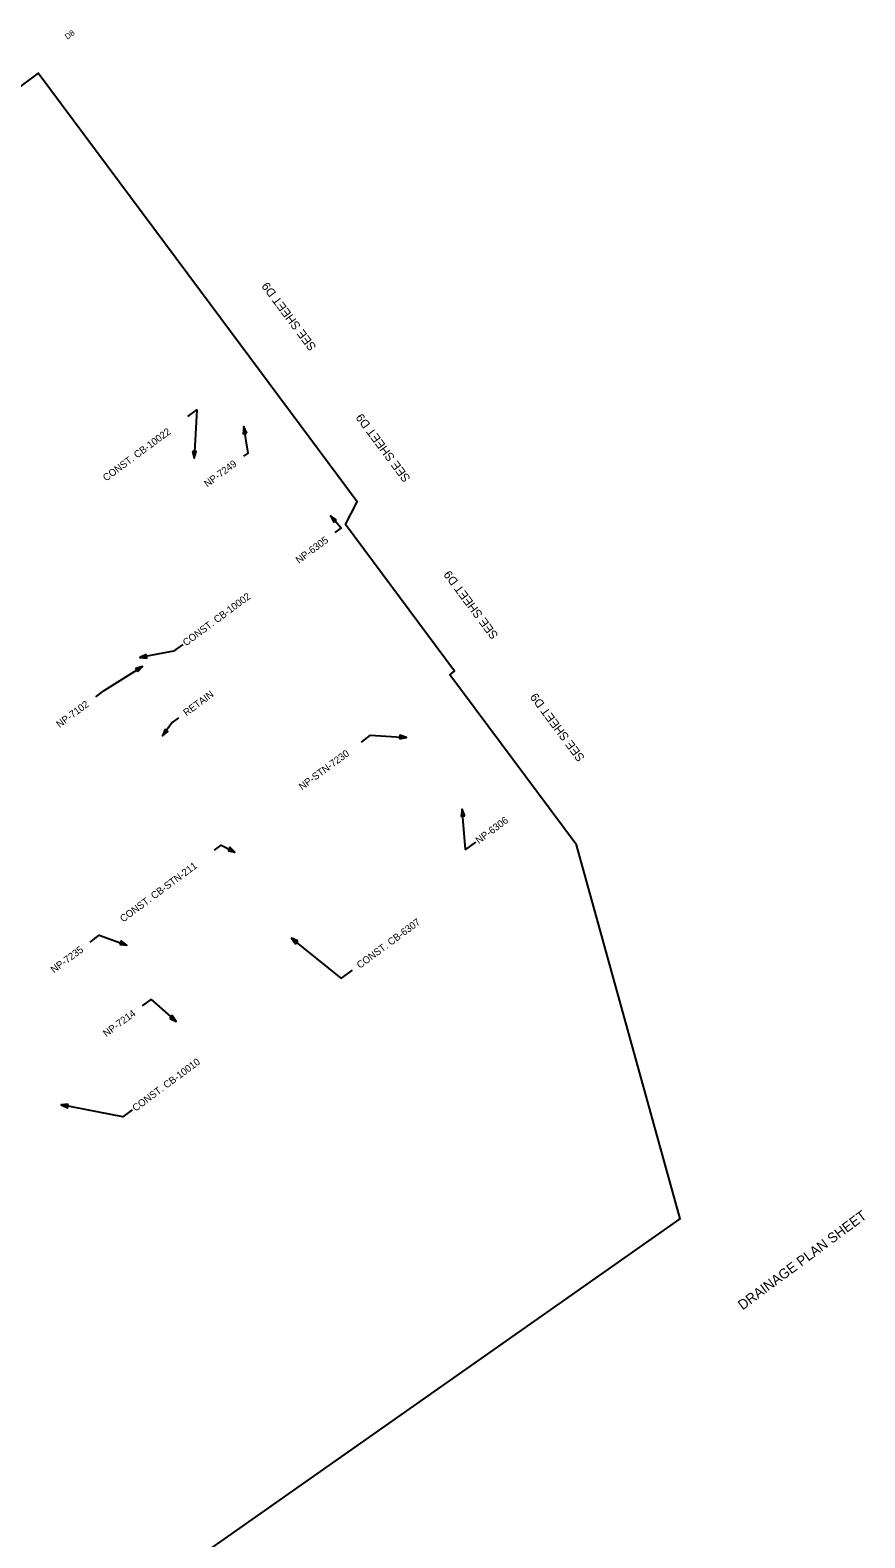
# Model space of a CAD drawing. Extents: x 1611197 to 1612945, y 1093889 to 1095652.
# Drawn here: x 1612358 to 1612945, y 1094591 to 1095652 of the extents above; entities that cross this region are included whole.
import ezdxf

# ---------------------------------------------------------------- set-up
doc = ezdxf.new("R2010")
doc.units = 0
for name, color, linetype in [('Plan_Clip', 7, 'Continuous'), ('RD_SHT_Bndy', 7, 'Continuous'), ('RD_SHT_MatchLine', 7, 'Continuous'), ('RD_TX_Drainage', 7, 'Continuous'), ('RD_TX_RoadID', 7, 'Continuous')]:
    doc.layers.add(name, color=color, linetype=linetype)

msp = doc.modelspace()

# ---------------------------------------------------------------- linework, layer by layer
at = {"layer": 'Plan_Clip'}
msp.add_lwpolyline([(1611268.7, 1094642.2), (1611330.5, 1094471.1), (1611497.9, 1094245.9), (1611487.3, 1094233.1), (1611570.5, 1094184.4), (1611553.7, 1094158.9), (1611675.8, 1094087.5), (1611739.8, 1094059.2), (1612815.4, 1094815.5), (1612742.5, 1095078.7), (1612653.4, 1095198.5), (1612656.9, 1095201.1), (1612580.2, 1095304.3), (1612588.4, 1095320.1), (1612485.6, 1095458.4), (1612364.1, 1095621.9), (1612226.9, 1095519.9), (1612207.6, 1095545.8), (1611204.4, 1094800.1), (1611197, 1094674.8)], close=True, dxfattribs=at)
msp.add_lwpolyline([(1611268.7, 1094642.2), (1611330.5, 1094471.1), (1611497.9, 1094245.9), (1611487.3, 1094233.1), (1611570.5, 1094184.4), (1611553.7, 1094158.9), (1611675.8, 1094087.5), (1611739.8, 1094059.2), (1612815.4, 1094815.5), (1612742.5, 1095078.7), (1612653.4, 1095198.5), (1612656.9, 1095201.1), (1612580.2, 1095304.3), (1612588.4, 1095320.1), (1612485.6, 1095458.4), (1612364.1, 1095621.9), (1612226.9, 1095519.9), (1612207.6, 1095545.8), (1611204.4, 1094800.1), (1611197, 1094674.8)], close=True, dxfattribs=at)
msp.add_lwpolyline([(1611268.7, 1094642.2), (1611330.5, 1094471.1), (1611497.9, 1094245.9), (1611487.3, 1094233.1), (1611570.5, 1094184.4), (1611553.7, 1094158.9), (1611675.8, 1094087.5), (1611739.8, 1094059.2), (1612815.4, 1094815.5), (1612742.5, 1095078.7), (1612653.4, 1095198.5), (1612656.9, 1095201.1), (1612580.2, 1095304.3), (1612588.4, 1095320.1), (1612485.6, 1095458.4), (1612364.1, 1095621.9), (1612226.9, 1095519.9), (1612207.6, 1095545.8), (1611204.4, 1094800.1), (1611197, 1094674.8)], close=True, dxfattribs=at)
msp.add_lwpolyline([(1611268.7, 1094642.2), (1611330.5, 1094471.1), (1611497.9, 1094245.9), (1611487.3, 1094233.1), (1611570.5, 1094184.4), (1611553.7, 1094158.9), (1611675.8, 1094087.5), (1611739.8, 1094059.2), (1612815.4, 1094815.5), (1612742.5, 1095078.7), (1612653.4, 1095198.5), (1612656.9, 1095201.1), (1612580.2, 1095304.3), (1612588.4, 1095320.1), (1612485.6, 1095458.4), (1612364.1, 1095621.9), (1612226.9, 1095519.9), (1612207.6, 1095545.8), (1611204.4, 1094800.1), (1611197, 1094674.8)], close=True, dxfattribs=at)
msp.add_lwpolyline([(1611268.7, 1094642.2), (1611330.5, 1094471.1), (1611497.9, 1094245.9), (1611487.3, 1094233.1), (1611570.5, 1094184.4), (1611553.7, 1094158.9), (1611675.8, 1094087.5), (1611739.8, 1094059.2), (1612815.4, 1094815.5), (1612742.5, 1095078.7), (1612653.4, 1095198.5), (1612656.9, 1095201.1), (1612580.2, 1095304.3), (1612588.4, 1095320.1), (1612485.6, 1095458.4), (1612364.1, 1095621.9), (1612226.9, 1095519.9), (1612207.6, 1095545.8), (1611204.4, 1094800.1), (1611197, 1094674.8)], close=True, dxfattribs=at)
msp.add_lwpolyline([(1611268.7, 1094642.2), (1611330.5, 1094471.1), (1611497.9, 1094245.9), (1611487.3, 1094233.1), (1611570.5, 1094184.4), (1611553.7, 1094158.9), (1611675.8, 1094087.5), (1611739.8, 1094059.2), (1612815.4, 1094815.5), (1612742.5, 1095078.7), (1612653.4, 1095198.5), (1612656.9, 1095201.1), (1612580.2, 1095304.3), (1612588.4, 1095320.1), (1612485.6, 1095458.4), (1612364.1, 1095621.9), (1612226.9, 1095519.9), (1612207.6, 1095545.8), (1611204.4, 1094800.1), (1611197, 1094674.8)], close=True, dxfattribs=at)
msp.add_lwpolyline([(1611268.7, 1094642.2), (1611330.5, 1094471.1), (1611497.9, 1094245.9), (1611487.3, 1094233.1), (1611570.5, 1094184.4), (1611553.7, 1094158.9), (1611675.8, 1094087.5), (1611739.8, 1094059.2), (1612815.4, 1094815.5), (1612742.5, 1095078.7), (1612653.4, 1095198.5), (1612656.9, 1095201.1), (1612580.2, 1095304.3), (1612588.4, 1095320.1), (1612485.6, 1095458.4), (1612364.1, 1095621.9), (1612226.9, 1095519.9), (1612207.6, 1095545.8), (1611204.4, 1094800.1), (1611197, 1094674.8)], close=True, dxfattribs=at)
msp.add_lwpolyline([(1611268.7, 1094642.2), (1611330.5, 1094471.1), (1611497.9, 1094245.9), (1611487.3, 1094233.1), (1611570.5, 1094184.4), (1611553.7, 1094158.9), (1611675.8, 1094087.5), (1611739.8, 1094059.2), (1612815.4, 1094815.5), (1612742.5, 1095078.7), (1612653.4, 1095198.5), (1612656.9, 1095201.1), (1612580.2, 1095304.3), (1612588.4, 1095320.1), (1612485.6, 1095458.4), (1612364.1, 1095621.9), (1612226.9, 1095519.9), (1612207.6, 1095545.8), (1611204.4, 1094800.1), (1611197, 1094674.8)], close=True, dxfattribs=at)
at = {"layer": 'RD_TX_Drainage'}
for points in [[(1612469.2, 1095380.2), (1612475.6, 1095385), (1612473.6, 1095350.8)], [(1612508.6, 1095352.3), (1612511.6, 1095354.5), (1612508.6, 1095373.1)], [(1612572.9, 1095298.6), (1612577.1, 1095301.7), (1612569.7, 1095310.3)], [(1612465.7, 1095219.8), (1612459.2, 1095215), (1612435.5, 1095210.5)], [(1612404.5, 1095183), (1612410.4, 1095187.4), (1612437.4, 1095204.3)], [(1612462.8, 1095168.1), (1612458.3, 1095164.8), (1612451.4, 1095155.4)], [(1612591.4, 1095151.1), (1612597.8, 1095155.9), (1612623.1, 1095154.3)], [(1612671.6, 1095080.6), (1612664.6, 1095075.5), (1612662.3, 1095103.8)], [(1612488.1, 1095074.9), (1612492.8, 1095078.4), (1612502.4, 1095073.6)], [(1612400.6, 1095010.3), (1612407, 1095015.1), (1612426.4, 1095008.2)], [(1612584.8, 1094990.5), (1612577.2, 1094984.8), (1612542.1, 1095013.1)], [(1612437.4, 1094965.4), (1612443.5, 1094969.9), (1612461, 1094954.4)], [(1612430.2, 1094892.2), (1612423.6, 1094887.2), (1612380.1, 1094895.8)]]:
    msp.add_lwpolyline(points, dxfattribs=at)
for points in [[(1612510.7, 1095368.5), (1612508.6, 1095373.1), (1612508.1, 1095368.1)], [(1612472.6, 1095355.7), (1612473.6, 1095350.8), (1612475.2, 1095355.5)], [(1612573.9, 1095307.4), (1612569.7, 1095310.3), (1612571.9, 1095305.8)], [(1612440, 1095212.7), (1612435.5, 1095210.5), (1612440.5, 1095210.1)], [(1612434, 1095200.7), (1612437.4, 1095204.3), (1612432.7, 1095202.9)], [(1612453.2, 1095160.1), (1612451.4, 1095155.4), (1612455.3, 1095158.5)], [(1612618.2, 1095153.3), (1612623.1, 1095154.3), (1612618.4, 1095155.9)], [(1612664, 1095099.1), (1612662.3, 1095103.8), (1612661.4, 1095098.9)], [(1612497.5, 1095074.6), (1612502.4, 1095073.6), (1612498.7, 1095077)], [(1612421.4, 1095008.6), (1612426.4, 1095008.2), (1612422.3, 1095011.1)], [(1612546.6, 1095011.1), (1612542.1, 1095013.1), (1612545, 1095009)], [(1612456.5, 1094956.6), (1612461, 1094954.4), (1612458.3, 1094958.6)], [(1612385.1, 1094896.1), (1612380.1, 1094895.8), (1612384.6, 1094893.6)]]:
    msp.add_lwpolyline(points, close=True, dxfattribs=at)

# ---------------------------------------------------------------- texts
at = {"layer": 'RD_SHT_Bndy'}
msp.add_text('D8', height=4, rotation=36.624, dxfattribs=at).set_placement((1612384.6, 1095645.4))
at = {"layer": 'RD_SHT_MatchLine'}
for p in [(1612559.9, 1095429.3), (1612626.1, 1095336.8), (1612687.9, 1095226.3), (1612748.7, 1095140.1)]:
    msp.add_text('SEE SHEET D9', height=6, rotation=126.6769, dxfattribs=at).set_placement(p)
at = {"layer": 'RD_TX_Drainage'}
for s, rotation, p in [('CONST. CB-10022', 36.624, (1612411.8, 1095334.4)), ('NP-7249', 36.624, (1612483, 1095330.2)), ('NP-6305', 36.624, (1612547.4, 1095276.5)), ('CONST. CB-10002', 36.624, (1612468, 1095218.4)), ('RETAIN', 36.624, (1612468.3, 1095169.1)), ('NP-7102', 36.6256, (1612379, 1095160.9)), ('NP-STN-7230', 36.624, (1612549.6, 1095117)), ('NP-6306', 36.624, (1612673.9, 1095079.2)), ('CONST. CB-STN-211', 36.624, (1612423.8, 1095024)), ('CONST. CB-6307', 36.624, (1612590.3, 1094991.4)), ('NP-7235', 36.624, (1612375.1, 1094988.2)), ('NP-7214', 36.624, (1612411.9, 1094943.3)), ('CONST. CB-10010', 36.624, (1612432.5, 1094890.8))]:
    msp.add_text(s, height=5, rotation=rotation, dxfattribs=at).set_placement(p)
at = {"layer": 'RD_TX_RoadID'}
msp.add_text('DRAINAGE PLAN SHEET', height=6.983, rotation=36.6256, dxfattribs=at).set_placement((1612859.4, 1094751))

doc.saveas('drawing.dxf')
